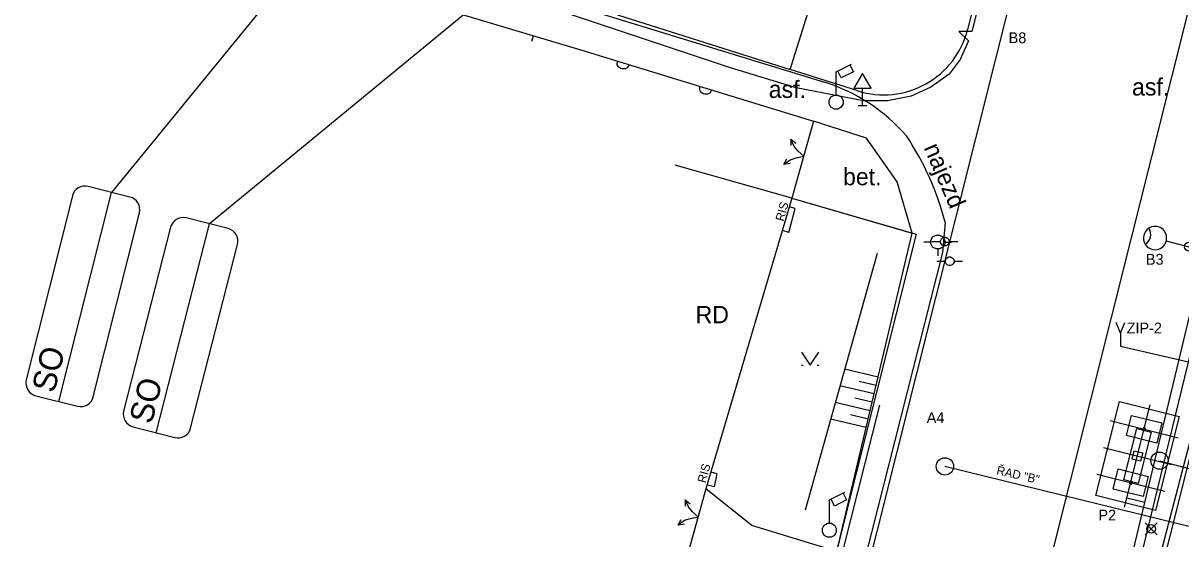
# Model space of a CAD drawing. Extents: x -733601 to -733291, y -1137892 to -1137187.
# Drawn here: x -733512.4 to -733445.4, y -1137582.3 to -1137552.5 of the extents above; entities that cross this region are included whole.
import ezdxf

# ---------------------------------------------------------------- set-up
doc = ezdxf.new("R2010")
doc.units = 0
for name, color, linetype in [('Default', 7, 'Continuous'), ('SIT_PROJ', 7, 'Continuous'), ('SIT_PUV_BUS', 7, 'Continuous')]:
    doc.layers.add(name, color=color, linetype=linetype)

# ---------------------------------------------------------------- blocks, each defined once
blk = doc.blocks.new('T_PS_1_1_1')
at = {"layer": 'Default'}
blk.add_line((-12.49, 3.72), (12.49, 3.72), dxfattribs=at)
for points in [[(10.99, 8), (-10.99, 8)], [(-12.49, 6.5), (-12.49, 1.5)], [(12.49, 1.5), (12.49, 6.5)], [(-10.99, 0), (10.99, 0)]]:
    blk.add_lwpolyline(points, dxfattribs=at)
for centre, start, end in [((-10.99, 6.5), 90, 180), ((10.99, 6.5), 0, 90), ((-10.99, 1.5), 180, 270), ((10.99, 1.5), 270, 360)]:
    blk.add_arc(centre, 1.5, start, end, dxfattribs=at)
blk.add_text('SO', height=2.7, dxfattribs=at).set_placement((-11.75, 4.47))
blk = doc.blocks.new('T_PS_1')
at = {"layer": 'Default'}
blk.add_line((-0.01249, 0.00372), (0.01249, 0.00372), dxfattribs=at)
for points in [[(0.01099, 0.008), (-0.01099, 0.008)], [(-0.01249, 0.0065), (-0.01249, 0.0015)], [(0.01249, 0.0015), (0.01249, 0.0065)], [(-0.01099, 0), (0.01099, 0)]]:
    blk.add_lwpolyline(points, dxfattribs=at)
for centre, start, end in [((-0.01099, 0.0065), 90, 180), ((0.01099, 0.0065), 0, 90), ((-0.01099, 0.0015), 180, 270), ((0.01099, 0.0015), 270, 360)]:
    blk.add_arc(centre, 0.0015, start, end, dxfattribs=at)
blk.add_text('SO', height=0.0027, dxfattribs=at).set_placement((-0.01175, 0.00447))
blk = doc.blocks.new('novy_s_2r')
at = {"layer": 'Default'}
for p in [(502.569, 387.82), (502.559, 384.813)]:
    blk.add_line(p, (502.564, 386.316), dxfattribs=at)
blk.add_circle((502.564, 386.316), 0.298, dxfattribs=at)
blk.add_circle((502.564, 386.316), 0.298, dxfattribs=at)
blk.add_circle((502.564, 386.316), 0.298, dxfattribs=at)
blk.add_circle((502.564, 386.316), 0.298, dxfattribs=at)
for centre, radius, start, end in [((502.571, 388.57), 0.75, 135.46827, 46.98278), ((502.571, 388.57), 0.75, 46.98373, 135.46732), ((502.571, 388.57), 0.75, 46.98373, 135.46732), ((502.55, 389.547), 0.684, 221.28424, 321.1668), ((502.55, 389.547), 0.684, 221.28424, 321.1668), ((502.556, 384.063), 0.75, 315.46827, 226.98278), ((502.577, 383.086), 0.684, 41.28424, 141.1668), ((502.577, 383.086), 0.684, 41.28424, 141.1668), ((502.556, 384.063), 0.75, 226.98373, 315.46732), ((502.556, 384.063), 0.75, 226.98373, 315.46732)]:
    blk.add_arc(centre, radius, start, end, dxfattribs=at)
blk = doc.blocks.new('VY1')
at = {"layer": 'Default'}
for q in [(-50, 275), (50, 275), (0, 0)]:
    blk.add_line((0, 150), q, dxfattribs=at)
blk = doc.blocks.new('POINT_DISPLAY')
at = {"layer": 'Default'}
for p, q in [((-0.7, -0.7), (0.7, 0.7)), ((-0.7, 0.7), (0.7, -0.7))]:
    blk.add_line(p, q, dxfattribs=at)
blk.add_circle((0, 0), 0.5, dxfattribs=at)
blk = doc.blocks.new('vytyc_bod_MP')
at = {"layer": 'Default'}
blk.add_blockref('POINT_DISPLAY', (0, 0), dxfattribs=at)

msp = doc.modelspace()

# ---------------------------------------------------------------- linework, layer by layer
at = {"layer": 'SIT_PROJ'}
for p, q in [((-733448.631, -1137580.497), (-733447.141, -1137574.561)), ((-733449.465, -1137575.484), (-733445.527, -1137576.472)), ((-733449.855, -1137577.035), (-733445.917, -1137578.024)), ((-733450.244, -1137578.587), (-733446.307, -1137579.576))]:
    msp.add_line(p, q, dxfattribs=at)
for points in [[(-733472.116, -1137618.354), (-733450.389, -1137531.821), (-733445.369, -1137510.61)], [(-733452.807, -1137531.541), (-733452.473, -1137533.224), (-733457.478, -1137552.932), (-733458.231, -1137552.948), (-733457.677, -1137553.487), (-733458.16, -1137554.567), (-733458.792, -1137555.404), (-733459.851, -1137556.172), (-733461, -1137556.688), (-733462.364, -1137556.956), (-733463.762, -1137556.963), (-733467.652, -1137556.198), (-733471.45, -1137555.042), (-733482.168, -1137551.478), (-733485.798, -1137550.329), (-733497.445, -1137546.837), (-733510.353, -1137542.814), (-733504.974, -1137526.312), (-733469.528, -1137537.558), (-733468.34, -1137535.665)], [(-733457.917, -1137622.364), (-733458.777, -1137620.095), (-733456.339, -1137614.218), (-733457.273, -1137613.333), (-733455.913, -1137612.939), (-733454.69, -1137608.9), (-733452.562, -1137600.661), (-733449.967, -1137590.732), (-733451.007, -1137589.721), (-733449.679, -1137589.475), (-733444.067, -1137566.075), (-733444.902, -1137565.405), (-733443.754, -1137565.269), (-733437.875, -1137541.673), (-733438.793, -1137541.042), (-733437.71, -1137541.027), (-733436.525, -1137536.63), (-733452.133, -1137532.662), (-733452.807, -1137531.541)], [(-733452.337, -1137531.363), (-733457.726, -1137552.828)], [(-733456.299, -1137623.235), (-733433.573, -1137532.72)], [(-733432.51, -1137534.385), (-733444.427, -1137581.731), (-733459.039, -1137578.132)], [(-733443.713, -1137537.937), (-733443.53, -1137546.097), (-733458.871, -1137607.201), (-733463.551, -1137615.482)], [(-733490.453, -1137541.633), (-733507.315, -1137562.262), (-733507.315, -1137562.262)], [(-733476.729, -1137547.92), (-733478.011, -1137551.972), (-733468, -1137555.139), (-733466.757, -1137551.211)], [(-733457.917, -1137622.364), (-733458.523, -1137621.757), (-733455.851, -1137614.377), (-733455.422, -1137613.019), (-733451.725, -1137599.481), (-733449.522, -1137590.912), (-733449.164, -1137589.482), (-733443.392, -1137565.741), (-733438.875, -1137547.904)], [(-733484.447, -1137549.937), (-733501.629, -1137564.088), (-733501.629, -1137564.088)], [(-733464.084, -1137556.378), (-733468, -1137555.139)], [(-733467.9, -1137562.59), (-733460.704, -1137564.688), (-733465.317, -1137583.062)], [(-733448.861, -1137571.168), (-733444.931, -1137572.072)], [(-733457.917, -1137622.364), (-733464.433, -1137621.3), (-733463.63, -1137616.478), (-733471.299, -1137614.635), (-733471.621, -1137613.836), (-733472.5, -1137612.391), (-733468.724, -1137597.945), (-733462.8, -1137574.579)], [(-733448.928, -1137574.37), (-733445.475, -1137575.237), (-733446.844, -1137580.688), (-733450.296, -1137579.821), (-733448.928, -1137574.371)], [(-733447.448, -1137576.058), (-733447.415, -1137575.929), (-733447.544, -1137575.897), (-733447.577, -1137576.026), (-733447.448, -1137576.058)], [(-733446.608, -1137577.804), (-733443.64, -1137578.577)], [(-733448.227, -1137579.162), (-733448.195, -1137579.033), (-733448.324, -1137579), (-733448.356, -1137579.129), (-733448.227, -1137579.162)], [(-733447.455, -1137580.217), (-733448.499, -1137579.972)]]:
    msp.add_lwpolyline(points, dxfattribs=at)
for points in [[(-733448.515, -1137576.341), (-733448.223, -1137575.177), (-733446.477, -1137575.616), (-733446.77, -1137576.78)], [(-733448.676, -1137578.912), (-733447.929, -1137575.937), (-733447.095, -1137576.147), (-733447.842, -1137579.121)], [(-733448.189, -1137577.711), (-733448.067, -1137577.226), (-733447.583, -1137577.348), (-733447.704, -1137577.833)], [(-733449.295, -1137579.444), (-733449.002, -1137578.281), (-733447.256, -1137578.719), (-733447.549, -1137579.883)]]:
    msp.add_lwpolyline(points, close=True, dxfattribs=at)
for centre in [(-733446.608, -1137577.804), (-733459.039, -1137578.133)]:
    msp.add_circle(centre, 0.5, dxfattribs=at)
msp.add_arc((-733462.576, -1137551.61), 5, 252.4471, 345.90587, dxfattribs=at)
at = {"layer": 'SIT_PUV_BUS'}
for p, q in [((-733494.85, -1137549.6), (-733480.06, -1137554.03)), ((-733479.43, -1137551.77), (-733466.01, -1137555.88)), ((-733482.88, -1137553.19), (-733482.981, -1137553.525)), ((-733480.06, -1137554.03), (-733466.64, -1137558.14)), ((-733478.015, -1137554.864), (-733478.005, -1137554.658)), ((-733477.949, -1137554.988), (-733478.015, -1137554.864)), ((-733477.82, -1137555.08), (-733477.949, -1137554.988)), ((-733477.725, -1137555.109), (-733477.82, -1137555.08)), ((-733477.566, -1137555.105), (-733477.725, -1137555.109)), ((-733477.442, -1137555.039), (-733477.566, -1137555.105)), ((-733477.335, -1137554.862), (-733477.442, -1137555.039)), ((-733465.34, -1137555.28), (-733464.44, -1137554.83)), ((-733464.54, -1137554.88), (-733464.34, -1137555.28)), ((-733465.34, -1137556.63), (-733465.34, -1137555.28)), ((-733465.04, -1137555.63), (-733465.24, -1137555.23)), ((-733464.34, -1137555.28), (-733465.04, -1137555.63)), ((-733463.81, -1137555.38), (-733464.31, -1137556.23)), ((-733463.31, -1137556.23), (-733463.81, -1137555.38)), ((-733473.235, -1137556.334), (-733473.225, -1137556.128)), ((-733473.169, -1137556.458), (-733473.235, -1137556.334)), ((-733473.04, -1137556.55), (-733473.169, -1137556.458)), ((-733472.662, -1137556.509), (-733472.786, -1137556.575)), ((-733472.555, -1137556.332), (-733472.662, -1137556.509)), ((-733464.31, -1137556.23), (-733463.31, -1137556.23)), ((-733463.81, -1137557.23), (-733463.81, -1137556.23)), ((-733472.945, -1137556.579), (-733473.04, -1137556.55)), ((-733472.786, -1137556.575), (-733472.945, -1137556.579)), ((-733465.74, -1137556.93), (-733465.64, -1137556.73)), ((-733465.74, -1137557.13), (-733465.74, -1137556.93)), ((-733465.64, -1137557.33), (-733465.74, -1137557.13)), ((-733465.64, -1137556.73), (-733465.44, -1137556.63)), ((-733465.44, -1137556.63), (-733465.24, -1137556.63)), ((-733465.24, -1137556.63), (-733465.04, -1137556.73)), ((-733465.04, -1137556.73), (-733464.94, -1137556.93)), ((-733464.94, -1137557.13), (-733465.04, -1137557.33)), ((-733464.94, -1137556.93), (-733464.94, -1137557.13)), ((-733465.44, -1137557.43), (-733465.64, -1137557.33)), ((-733465.24, -1137557.43), (-733465.44, -1137557.43)), ((-733465.04, -1137557.33), (-733465.24, -1137557.43)), ((-733464.06, -1137557.23), (-733463.56, -1137557.23)), ((-733466.64, -1137558.14), (-733467.9, -1137562.59)), ((-733463.58, -1137559.12), (-733466.64, -1137558.14)), ((-733467.776, -1137559.595), (-733467.97, -1137559.177)), ((-733467.97, -1137559.177), (-733467.968, -1137559.541)), ((-733467.97, -1137559.177), (-733467.673, -1137559.416)), ((-733461.81, -1137561.64), (-733463.58, -1137559.12)), ((-733467.541, -1137559.869), (-733467.776, -1137559.595)), ((-733467.21, -1137560.17), (-733467.541, -1137559.869)), ((-733468.376, -1137560.621), (-733468.185, -1137560.311)), ((-733468.376, -1137560.621), (-733467.992, -1137560.366)), ((-733467.992, -1137560.366), (-733467.649, -1137560.254)), ((-733467.649, -1137560.254), (-733467.21, -1137560.17)), ((-733467.9, -1137562.59), (-733474.66, -1137560.69)), ((-733468.376, -1137560.621), (-733467.998, -1137560.572)), ((-733460.94, -1137564.62), (-733461.81, -1137561.64)), ((-733467.9, -1137562.59), (-733472.88, -1137579.44)), ((-733468.07, -1137564.58), (-733467.71, -1137563.2)), ((-733467.71, -1137563.2), (-733468.05, -1137563.1)), ((-733467.9, -1137562.59), (-733460.94, -1137564.62)), ((-733468.07, -1137564.58), (-733468.45, -1137564.47)), ((-733459.02, -1137563.99), (-733459.18, -1137565.75)), ((-733465.29, -1137583.07), (-733460.94, -1137564.62)), ((-733459.85, -1137565.14), (-733460.25, -1137565.14)), ((-733459.85, -1137565.04), (-733459.75, -1137564.84)), ((-733459.85, -1137565.24), (-733459.85, -1137565.04)), ((-733459.75, -1137565.44), (-733459.85, -1137565.24)), ((-733459.79, -1137565.11), (-733459.29, -1137565.11)), ((-733459.75, -1137564.84), (-733459.55, -1137564.74)), ((-733459.55, -1137564.74), (-733459.35, -1137564.74)), ((-733459.35, -1137564.74), (-733459.15, -1137564.84)), ((-733459.29, -1137565.06), (-733459.24, -1137564.96)), ((-733459.29, -1137565.16), (-733459.29, -1137565.06)), ((-733459.24, -1137565.26), (-733459.29, -1137565.16)), ((-733459.24, -1137564.96), (-733459.19, -1137564.91)), ((-733459.19, -1137564.91), (-733459.09, -1137564.86)), ((-733459.15, -1137564.84), (-733459.05, -1137565.04)), ((-733459.05, -1137565.24), (-733459.15, -1137565.44)), ((-733459.09, -1137564.86), (-733458.99, -1137564.86)), ((-733459.05, -1137565.04), (-733459.05, -1137565.24)), ((-733459.05, -1137565.14), (-733458.65, -1137565.14)), ((-733458.99, -1137564.86), (-733458.89, -1137564.91)), ((-733458.89, -1137564.91), (-733458.84, -1137564.96)), ((-733458.84, -1137564.96), (-733458.79, -1137565.06)), ((-733458.79, -1137565.16), (-733458.84, -1137565.26)), ((-733458.79, -1137565.06), (-733458.79, -1137565.16)), ((-733458.79, -1137565.11), (-733458.29, -1137565.11)), ((-733462.97, -1137565.81), (-733467.13, -1137580.67)), ((-733459.18, -1137565.75), (-733463.31, -1137582.04)), ((-733459.55, -1137565.54), (-733459.75, -1137565.44)), ((-733459.35, -1137565.54), (-733459.55, -1137565.54)), ((-733459.45, -1137565.54), (-733459.45, -1137565.94)), ((-733459.15, -1137565.44), (-733459.35, -1137565.54)), ((-733459.19, -1137565.31), (-733459.24, -1137565.26)), ((-733459.09, -1137565.36), (-733459.19, -1137565.31)), ((-733458.99, -1137565.36), (-733459.09, -1137565.36)), ((-733458.89, -1137565.31), (-733458.99, -1137565.36)), ((-733458.84, -1137565.26), (-733458.89, -1137565.31)), ((-733459.51, -1137566.25), (-733459.01, -1137566.25)), ((-733459.01, -1137566.2), (-733458.96, -1137566.1)), ((-733459.01, -1137566.3), (-733459.01, -1137566.2)), ((-733458.96, -1137566.4), (-733459.01, -1137566.3)), ((-733458.96, -1137566.1), (-733458.91, -1137566.05)), ((-733458.91, -1137566.45), (-733458.96, -1137566.4)), ((-733458.91, -1137566.05), (-733458.81, -1137566)), ((-733458.81, -1137566.5), (-733458.91, -1137566.45)), ((-733458.81, -1137566), (-733458.71, -1137566)), ((-733458.71, -1137566.5), (-733458.81, -1137566.5)), ((-733458.71, -1137566), (-733458.61, -1137566.05)), ((-733458.61, -1137566.45), (-733458.71, -1137566.5)), ((-733458.61, -1137566.05), (-733458.56, -1137566.1)), ((-733458.56, -1137566.4), (-733458.61, -1137566.45)), ((-733458.56, -1137566.1), (-733458.51, -1137566.2)), ((-733458.51, -1137566.3), (-733458.56, -1137566.4)), ((-733458.51, -1137566.2), (-733458.51, -1137566.3)), ((-733458.51, -1137566.25), (-733458.01, -1137566.25)), ((-733442.47, -1137567.55), (-733446.56, -1137583.19)), ((-733467.34, -1137571.51), (-733466.84, -1137572.26)), ((-733466.84, -1137572.26), (-733466.34, -1137571.51)), ((-733467.34, -1137572.26), (-733467.24, -1137572.26)), ((-733466.44, -1137572.26), (-733466.34, -1137572.26)), ((-733462.91, -1137572.96), (-733464.85, -1137572.5)), ((-733463.02, -1137573.45), (-733464, -1137573.22)), ((-733463.14, -1137573.93), (-733465.12, -1137573.47)), ((-733463.37, -1137574.91), (-733465.39, -1137574.43)), ((-733463.25, -1137574.42), (-733464.25, -1137574.19)), ((-733463.48, -1137575.39), (-733464.5, -1137575.15)), ((-733463.6, -1137575.88), (-733465.66, -1137575.4)), ((-733472.24, -1137578.56), (-733472.58, -1137578.46)), ((-733472.24, -1137578.56), (-733472.4, -1137579.32)), ((-733472.4, -1137579.32), (-733472.8, -1137579.2)), ((-733472.88, -1137579.44), (-733474.01, -1137583.46)), ((-733470.22, -1137581.56), (-733472.88, -1137579.44)), ((-733465.73, -1137580.08), (-733464.83, -1137579.63)), ((-733464.93, -1137579.68), (-733464.73, -1137580.08)), ((-733473.895, -1137580.485), (-733474.089, -1137580.067)), ((-733474.089, -1137580.067), (-733474.088, -1137580.431)), ((-733474.089, -1137580.067), (-733473.793, -1137580.306)), ((-733473.661, -1137580.759), (-733473.895, -1137580.485)), ((-733465.73, -1137581.43), (-733465.73, -1137580.08)), ((-733465.43, -1137580.43), (-733465.63, -1137580.03)), ((-733464.73, -1137580.08), (-733465.43, -1137580.43)), ((-733474.496, -1137581.511), (-733474.305, -1137581.201)), ((-733474.496, -1137581.511), (-733474.112, -1137581.255)), ((-733474.112, -1137581.255), (-733473.769, -1137581.144)), ((-733473.769, -1137581.144), (-733473.33, -1137581.06)), ((-733473.33, -1137581.06), (-733473.661, -1137580.759)), ((-733474.496, -1137581.511), (-733474.118, -1137581.461)), ((-733465.29, -1137583.07), (-733470.22, -1137581.56)), ((-733466.13, -1137581.73), (-733466.03, -1137581.53)), ((-733466.13, -1137581.93), (-733466.13, -1137581.73)), ((-733466.03, -1137582.13), (-733466.13, -1137581.93)), ((-733466.03, -1137581.53), (-733465.83, -1137581.43)), ((-733465.83, -1137581.43), (-733465.63, -1137581.43)), ((-733465.63, -1137581.43), (-733465.43, -1137581.53)), ((-733465.43, -1137581.53), (-733465.33, -1137581.73)), ((-733465.33, -1137581.93), (-733465.43, -1137582.13)), ((-733465.33, -1137581.73), (-733465.33, -1137581.93)), ((-733465.83, -1137582.23), (-733466.03, -1137582.13)), ((-733465.63, -1137582.23), (-733465.83, -1137582.23)), ((-733465.43, -1137582.13), (-733465.63, -1137582.23)), ((-733463.31, -1137582.04), (-733464.48, -1137586.57))]:
    msp.add_line(p, q, dxfattribs=at)
for centre, radius, start, end in [((-733469.07, -1137565.71), 10.296, 40.72459, 72.7404), ((-733474.74, -1137568.05), 16.234, 14.47927, 33.90659)]:
    msp.add_arc(centre, radius, start, end, dxfattribs=at)

# ---------------------------------------------------------------- block references
at = {"layer": 'SIT_PROJ'}
for name, p, xscale, yscale, rotation in [('T_PS_1', (-733507.03, -1137568.769), 499.9999999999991, 499.9999999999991, 75.93557209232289), ('T_PS_1_1_1', (-733501.371, -1137570.597), 0.4999999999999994, 0.4999999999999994, 75.68569569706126), ('novy_s_2r', (-733217.423, -1138088.588), 0.9000000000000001, 0.8999999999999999, 75.95014741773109)]:
    msp.add_blockref(name, p, dxfattribs=dict(at, xscale=xscale, yscale=yscale, rotation=rotation))
for name, p, xscale, yscale in [('VY1', (-733448.861, -1137571.168), 0.005, 0.005), ('vytyc_bod_MP', (-733447.087, -1137581.755), 0.5, 0.5)]:
    msp.add_blockref(name, p, dxfattribs=dict(at, xscale=xscale, yscale=yscale))

# ---------------------------------------------------------------- texts
for s, height, rotation, p in [('B8', 0.625, 360, (-733455.347, -1137553.616)), ('B3', 0.625, 360, (-733447.396, -1137566.45)), ('ZIP-2', 0.625, 360, (-733448.51, -1137570.43)), ('A4', 0.625, 360, (-733460.091, -1137575.62)), ('ŘAD "B"', 0.5, 347.02682, (-733456.081, -1137578.583)), ('P2', 0.625, 360, (-733450.147, -1137581.267))]:
    msp.add_text(s, height=height, rotation=rotation, dxfattribs=at).set_placement(p)
at = {"layer": 'SIT_PUV_BUS'}
for s, p in [('asf.', (-733469.24, -1137556.79)), ('asf.', (-733448.2, -1137556.65)), ('bet.', (-733464.94, -1137561.85)), ('RD', (-733473.48, -1137569.84))]:
    msp.add_text(s, height=1, dxfattribs=at).set_placement(p)
for s, height, rotation, p in [('najezd', 1, 293.4, (-733460.28, -1137559.67)), ('RIS', 0.5, 74.7, (-733468.38, -1137563.97)), ('RIS', 0.5, 74.7, (-733472.9, -1137579.13))]:
    msp.add_text(s, height=height, rotation=rotation, dxfattribs=at).set_placement(p)

doc.saveas('drawing.dxf')
